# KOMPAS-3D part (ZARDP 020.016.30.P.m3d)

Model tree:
1. Плоскость XY
2. Плоскость ZX
3. Плоскость ZY
4. Ось X
5. Ось Y
6. Ось Z
7. Начало координат
8. Смещенная плоскость:2
     Расстояние = 60
9. Смещенная плоскость:3
     Расстояние = 102
10. Смещенная плоскость:4
     Расстояние = 102
11. Булева операция:1
12. Булева операция:2
13. Булева операция:3
14. Булева операция:4
15. Булева операция:5
16. Булева операция:6
